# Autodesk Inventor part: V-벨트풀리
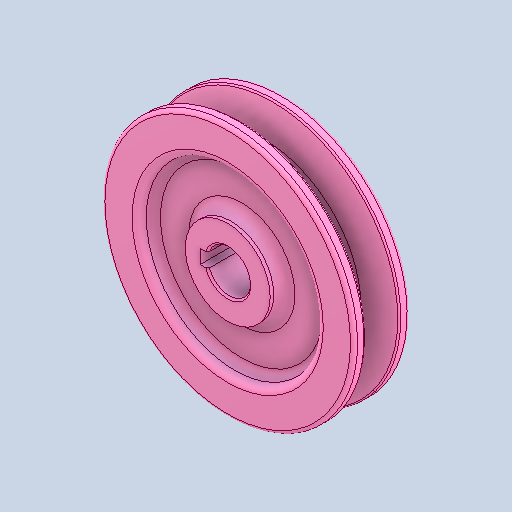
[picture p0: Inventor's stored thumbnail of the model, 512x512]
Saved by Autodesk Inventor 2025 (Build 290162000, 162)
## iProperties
Created: 2024-08
Part Number: V-벨트풀리
Material: 강철, 연강
Document SubType Name: Modeling
Designer: samsung
Density: 7.86 g/cm^3
Appearance: 기본값
Author: jhkim
Sending System: Autodesk Inventor 2025
Preprocessor: ST-DEVELOPER v20
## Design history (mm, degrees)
feature "Solid1"
node "솔리드1"
